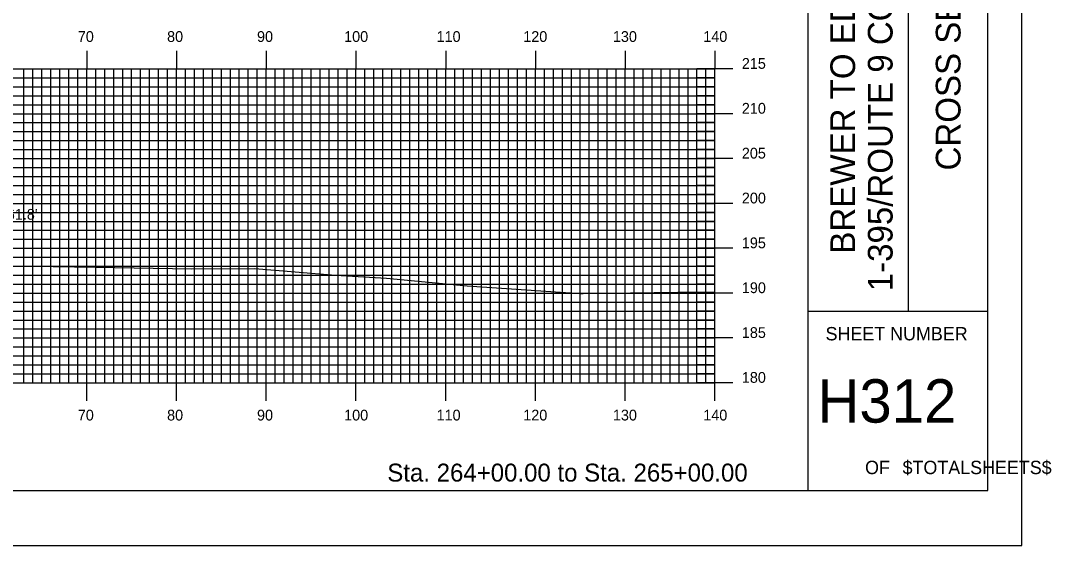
# Model space of a CAD drawing. Extents: x 1807045 to 1807388, y 442591 to 442811.
# Drawn here: x 1807273.4 to 1807388.3, y 442590.5 to 442649 of the extents above; entities that cross this region are included whole.
import ezdxf

# ---------------------------------------------------------------- set-up
doc = ezdxf.new("R2010")
doc.units = 0
for name, color, linetype in [('BORDER', 7, 'Continuous'), ('D_Text_Standard', 7, 'Continuous'), ('H_V ANNOTATION', 7, 'Continuous'), ('MAJOR', 7, 'Continuous'), ('MINOR', 7, 'Continuous'), ('PLOT BOUNDARY', 7, 'Continuous'), ('S_Roadway_Centerline', 7, 'Continuous')]:
    doc.layers.add(name, color=color, linetype=linetype)

msp = doc.modelspace()

# ---------------------------------------------------------------- linework, layer by layer
at = {"layer": 'BORDER'}
for p, q in [((1807361.16, 442596.67), (1807361.16, 442806.67)), ((1807372.34, 442616.67), (1807372.34, 442686.67)), ((1807361.16, 442616.67), (1807381.16, 442616.67))]:
    msp.add_line(p, q, dxfattribs=at)
msp.add_lwpolyline([(1807061.16, 442596.67), (1807381.16, 442596.67), (1807381.16, 442806.67), (1807061.16, 442806.67)], close=True, dxfattribs=at)
at = {"layer": 'MAJOR'}
for p, q in [((1807280.76, 442645.67), (1807280.76, 442643.67)), ((1807290.76, 442645.67), (1807290.76, 442643.67)), ((1807300.76, 442645.67), (1807300.76, 442643.67)), ((1807310.76, 442645.67), (1807310.76, 442643.67)), ((1807320.76, 442645.67), (1807320.76, 442643.67)), ((1807330.76, 442645.67), (1807330.76, 442643.67)), ((1807340.76, 442645.67), (1807340.76, 442643.67)), ((1807350.76, 442645.67), (1807350.76, 442643.67)), ((1807070.76, 442643.67), (1807350.76, 442643.67)), ((1807070.76, 442643.67), (1807350.76, 442643.67)), ((1807280.76, 442608.67), (1807280.76, 442643.67)), ((1807290.76, 442608.67), (1807290.76, 442643.67)), ((1807300.76, 442608.67), (1807300.76, 442643.67)), ((1807310.76, 442608.67), (1807310.76, 442643.67)), ((1807320.76, 442608.67), (1807320.76, 442643.67)), ((1807330.76, 442608.67), (1807330.76, 442643.67)), ((1807340.76, 442608.67), (1807340.76, 442643.67)), ((1807352.76, 442643.67), (1807348.75, 442643.67)), ((1807350.76, 442608.67), (1807350.76, 442643.67)), ((1807350.76, 442608.67), (1807350.76, 442643.67)), ((1807070.76, 442638.67), (1807350.76, 442638.67)), ((1807352.76, 442638.67), (1807348.75, 442638.67)), ((1807070.76, 442633.67), (1807350.76, 442633.67)), ((1807352.76, 442633.67), (1807348.75, 442633.67)), ((1807070.76, 442628.67), (1807350.76, 442628.67)), ((1807352.76, 442628.67), (1807348.75, 442628.67)), ((1807070.76, 442623.67), (1807350.76, 442623.67)), ((1807352.76, 442623.67), (1807348.75, 442623.67)), ((1807070.76, 442618.67), (1807350.76, 442618.67)), ((1807352.76, 442618.67), (1807348.75, 442618.67)), ((1807070.76, 442613.67), (1807350.76, 442613.67)), ((1807352.76, 442613.67), (1807348.75, 442613.67)), ((1807070.76, 442608.67), (1807350.76, 442608.67)), ((1807070.76, 442608.67), (1807350.76, 442608.67)), ((1807280.76, 442606.66), (1807280.76, 442608.67)), ((1807290.76, 442606.66), (1807290.76, 442608.67)), ((1807300.76, 442606.66), (1807300.76, 442608.67)), ((1807310.76, 442606.66), (1807310.76, 442608.67)), ((1807320.76, 442606.66), (1807320.76, 442608.67)), ((1807330.76, 442606.66), (1807330.76, 442608.67)), ((1807340.76, 442606.66), (1807340.76, 442608.67)), ((1807352.76, 442608.67), (1807348.75, 442608.67)), ((1807350.76, 442606.66), (1807350.76, 442608.67))]:
    msp.add_line(p, q, dxfattribs=at)
at = {"layer": 'MINOR'}
for p, q in [((1807070.76, 442642.67), (1807350.76, 442642.67)), ((1807273.76, 442608.67), (1807273.76, 442643.67)), ((1807274.76, 442608.67), (1807274.76, 442643.67)), ((1807275.76, 442608.67), (1807275.76, 442643.67)), ((1807276.76, 442608.67), (1807276.76, 442643.67)), ((1807277.76, 442608.67), (1807277.76, 442643.67)), ((1807278.76, 442608.67), (1807278.76, 442643.67)), ((1807279.76, 442608.67), (1807279.76, 442643.67)), ((1807281.76, 442608.67), (1807281.76, 442643.67)), ((1807282.76, 442608.67), (1807282.76, 442643.67)), ((1807283.76, 442608.67), (1807283.76, 442643.67)), ((1807284.76, 442608.67), (1807284.76, 442643.67)), ((1807285.76, 442608.67), (1807285.76, 442643.67)), ((1807286.76, 442608.67), (1807286.76, 442643.67)), ((1807287.76, 442608.67), (1807287.76, 442643.67)), ((1807288.76, 442608.67), (1807288.76, 442643.67)), ((1807289.76, 442608.67), (1807289.76, 442643.67)), ((1807291.76, 442608.67), (1807291.76, 442643.67)), ((1807292.76, 442608.67), (1807292.76, 442643.67)), ((1807293.76, 442608.67), (1807293.76, 442643.67)), ((1807294.76, 442608.67), (1807294.76, 442643.67)), ((1807295.76, 442608.67), (1807295.76, 442643.67)), ((1807296.76, 442608.67), (1807296.76, 442643.67)), ((1807297.76, 442608.67), (1807297.76, 442643.67)), ((1807298.76, 442608.67), (1807298.76, 442643.67)), ((1807299.76, 442608.67), (1807299.76, 442643.67)), ((1807301.76, 442608.67), (1807301.76, 442643.67)), ((1807302.76, 442608.67), (1807302.76, 442643.67)), ((1807303.76, 442608.67), (1807303.76, 442643.67)), ((1807304.76, 442608.67), (1807304.76, 442643.67)), ((1807305.76, 442608.67), (1807305.76, 442643.67)), ((1807306.76, 442608.67), (1807306.76, 442643.67)), ((1807307.76, 442608.67), (1807307.76, 442643.67)), ((1807308.76, 442608.67), (1807308.76, 442643.67)), ((1807309.76, 442608.67), (1807309.76, 442643.67)), ((1807311.76, 442608.67), (1807311.76, 442643.67)), ((1807312.76, 442608.67), (1807312.76, 442643.67)), ((1807313.76, 442608.67), (1807313.76, 442643.67)), ((1807314.76, 442608.67), (1807314.76, 442643.67)), ((1807315.76, 442608.67), (1807315.76, 442643.67)), ((1807316.76, 442608.67), (1807316.76, 442643.67)), ((1807317.76, 442608.67), (1807317.76, 442643.67)), ((1807318.76, 442608.67), (1807318.76, 442643.67)), ((1807319.76, 442608.67), (1807319.76, 442643.67)), ((1807321.76, 442608.67), (1807321.76, 442643.67)), ((1807322.76, 442608.67), (1807322.76, 442643.67)), ((1807323.76, 442608.67), (1807323.76, 442643.67)), ((1807324.76, 442608.67), (1807324.76, 442643.67)), ((1807325.76, 442608.67), (1807325.76, 442643.67)), ((1807326.76, 442608.67), (1807326.76, 442643.67)), ((1807327.76, 442608.67), (1807327.76, 442643.67)), ((1807328.76, 442608.67), (1807328.76, 442643.67)), ((1807329.76, 442608.67), (1807329.76, 442643.67)), ((1807331.76, 442608.67), (1807331.76, 442643.67)), ((1807332.76, 442608.67), (1807332.76, 442643.67)), ((1807333.76, 442608.67), (1807333.76, 442643.67)), ((1807334.76, 442608.67), (1807334.76, 442643.67)), ((1807335.76, 442608.67), (1807335.76, 442643.67)), ((1807336.76, 442608.67), (1807336.76, 442643.67)), ((1807337.76, 442608.67), (1807337.76, 442643.67)), ((1807338.76, 442608.67), (1807338.76, 442643.67)), ((1807339.76, 442608.67), (1807339.76, 442643.67)), ((1807341.76, 442608.67), (1807341.76, 442643.67)), ((1807342.76, 442608.67), (1807342.76, 442643.67)), ((1807343.76, 442608.67), (1807343.76, 442643.67)), ((1807344.76, 442608.67), (1807344.76, 442643.67)), ((1807345.76, 442608.67), (1807345.76, 442643.67)), ((1807346.76, 442608.67), (1807346.76, 442643.67)), ((1807347.76, 442608.67), (1807347.76, 442643.67)), ((1807350.76, 442642.67), (1807348.75, 442642.67)), ((1807348.76, 442608.67), (1807348.76, 442643.67)), ((1807349.76, 442608.67), (1807349.76, 442643.67)), ((1807070.76, 442641.67), (1807350.76, 442641.67)), ((1807350.76, 442641.67), (1807348.75, 442641.67)), ((1807070.76, 442640.67), (1807350.76, 442640.67)), ((1807350.76, 442640.67), (1807348.75, 442640.67)), ((1807070.76, 442639.67), (1807350.76, 442639.67)), ((1807350.76, 442639.67), (1807348.75, 442639.67)), ((1807070.76, 442637.67), (1807350.76, 442637.67)), ((1807350.76, 442637.67), (1807348.75, 442637.67)), ((1807070.76, 442636.67), (1807350.76, 442636.67)), ((1807350.76, 442636.67), (1807348.75, 442636.67)), ((1807070.76, 442635.67), (1807350.76, 442635.67)), ((1807070.76, 442634.67), (1807350.76, 442634.67)), ((1807350.76, 442635.67), (1807348.75, 442635.67)), ((1807350.76, 442634.67), (1807348.75, 442634.67)), ((1807070.76, 442632.67), (1807350.76, 442632.67)), ((1807350.76, 442632.67), (1807348.75, 442632.67)), ((1807070.76, 442631.67), (1807350.76, 442631.67)), ((1807350.76, 442631.67), (1807348.75, 442631.67)), ((1807070.76, 442630.67), (1807350.76, 442630.67)), ((1807350.76, 442630.67), (1807348.75, 442630.67)), ((1807070.76, 442629.67), (1807350.76, 442629.67)), ((1807350.76, 442629.67), (1807348.75, 442629.67)), ((1807070.76, 442627.67), (1807350.76, 442627.67)), ((1807350.76, 442627.67), (1807348.75, 442627.67)), ((1807070.76, 442626.67), (1807350.76, 442626.67)), ((1807350.76, 442626.67), (1807348.75, 442626.67)), ((1807070.76, 442625.67), (1807350.76, 442625.67)), ((1807350.76, 442625.67), (1807348.75, 442625.67)), ((1807070.76, 442624.67), (1807350.76, 442624.67)), ((1807350.76, 442624.67), (1807348.75, 442624.67)), ((1807070.76, 442622.67), (1807350.76, 442622.67)), ((1807350.76, 442622.67), (1807348.75, 442622.67)), ((1807070.76, 442621.67), (1807350.76, 442621.67)), ((1807350.76, 442621.67), (1807348.75, 442621.67)), ((1807070.76, 442620.67), (1807350.76, 442620.67)), ((1807070.76, 442619.67), (1807350.76, 442619.67)), ((1807350.76, 442620.67), (1807348.75, 442620.67)), ((1807350.76, 442619.67), (1807348.75, 442619.67)), ((1807070.76, 442617.67), (1807350.76, 442617.67)), ((1807350.76, 442617.67), (1807348.75, 442617.67)), ((1807070.76, 442616.67), (1807350.76, 442616.67)), ((1807350.76, 442616.67), (1807348.75, 442616.67)), ((1807070.76, 442615.67), (1807350.76, 442615.67)), ((1807350.76, 442615.67), (1807348.75, 442615.67)), ((1807070.76, 442614.67), (1807350.76, 442614.67)), ((1807350.76, 442614.67), (1807348.75, 442614.67)), ((1807070.76, 442612.67), (1807350.76, 442612.67)), ((1807070.76, 442611.67), (1807350.76, 442611.67)), ((1807350.76, 442612.67), (1807348.75, 442612.67)), ((1807350.76, 442611.67), (1807348.75, 442611.67)), ((1807070.76, 442610.67), (1807350.76, 442610.67)), ((1807350.76, 442610.67), (1807348.75, 442610.67)), ((1807070.76, 442609.67), (1807350.76, 442609.67)), ((1807350.76, 442609.67), (1807348.75, 442609.67))]:
    msp.add_line(p, q, dxfattribs=at)
at = {"layer": 'PLOT BOUNDARY'}
msp.add_lwpolyline([(1807044.97, 442590.55), (1807384.97, 442590.55), (1807384.97, 442810.55), (1807044.97, 442810.55)], close=True, dxfattribs=at)
at = {"layer": 'S_Roadway_Centerline'}
msp.add_lwpolyline([(1807269.79, 442621.76), (1807281.76, 442621.55), (1807292.43, 442621.39), (1807299.47, 442621.43), (1807308.47, 442620.68), (1807314.15, 442620.35), (1807323.14, 442619.48), (1807335.74, 442618.64), (1807336.07, 442618.63), (1807346.61, 442618.78), (1807350.76, 442618.76)], dxfattribs=at)

# ---------------------------------------------------------------- texts
at = {"layer": 'BORDER'}
for s, p in [('1-395/ROUTE 9 CONNECTOR', (1807370.56, 442618.87)), ('BREWER TO EDDINGTON', (1807366.38, 442623.07)), ('CROSS SECTIONS', (1807378.13, 442632.34))]:
    msp.add_text(s, height=2.7557, rotation=90, dxfattribs=at).set_placement(p)
for s, height, p in [('SHEET NUMBER', 1.4905, (1807363.09, 442613.4)), ('H312', 4.839, (1807362.19, 442604.23)), ('$TOTALSHEETS$', 1.4905, (1807371.67, 442598.49)), ('OF', 1.491, (1807367.49, 442598.49))]:
    msp.add_text(s, height=height, dxfattribs=at).set_placement(p)
at = {"layer": 'D_Text_Standard'}
msp.add_text("61.8'", height=1.2, dxfattribs=at).set_placement((1807271.85, 442626.85))
at = {"layer": 'H_V ANNOTATION'}
for s, height, p in [('70', 1.2, (1807279.76, 442646.67)), ('80', 1.2, (1807289.71, 442646.67)), ('90', 1.2, (1807299.73, 442646.67)), ('100', 1.2, (1807309.44, 442646.67)), ('110', 1.2, (1807319.74, 442646.67)), ('120', 1.2, (1807329.4, 442646.67)), ('130', 1.2, (1807339.39, 442646.67)), ('140', 1.2, (1807349.46, 442646.67)), ('215', 1.2, (1807353.76, 442643.67)), ('210', 1.2, (1807353.76, 442638.67)), ('205', 1.2, (1807353.76, 442633.67)), ('200', 1.2, (1807353.76, 442628.67)), ('195', 1.2, (1807353.76, 442623.67)), ('190', 1.2, (1807353.76, 442618.67)), ('185', 1.2, (1807353.76, 442613.67)), ('180', 1.2, (1807353.76, 442608.67)), ('70', 1.2, (1807279.76, 442604.47)), ('80', 1.2, (1807289.71, 442604.47)), ('90', 1.2, (1807299.73, 442604.47)), ('100', 1.2, (1807309.44, 442604.47)), ('110', 1.2, (1807319.74, 442604.47)), ('120', 1.2, (1807329.4, 442604.47)), ('130', 1.2, (1807339.39, 442604.47)), ('140', 1.2, (1807349.46, 442604.47)), ('Sta. 264+00.00 to Sta. 265+00.00', 2.0004, (1807314.25, 442597.66))]:
    msp.add_text(s, height=height, dxfattribs=at).set_placement(p)

doc.saveas('drawing.dxf')
